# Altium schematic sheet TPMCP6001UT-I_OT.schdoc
size 127 x 101 mm
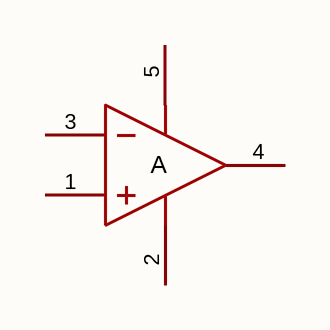
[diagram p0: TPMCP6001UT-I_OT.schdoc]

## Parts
U?  tpmcp6001ut-i/ot  [SOT-23-5_L2.9-W1.6-P0.95-LS2.8-BR]  (value not drawn)

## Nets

Not connected (* = marked no-connect by the designer): U? 1(+IN) 2(-VS) 3(-IN) 4(OUT) 5(+VS)

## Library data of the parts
U? = tpmcp6001ut-i/ot: 放大器数:1;轨到轨:轨到轨输入,轨到轨输出;增益带宽积(GBW):1MHz;输入失调电压(Vos):5mV;压摆率(SR):4.5V/us;输入偏置电流(Ib):10pA;; Manufacturer: TECH PUBLIC(台舟); AddInBom: yes; ModelId: 7ba65df16e7b4570af156e925f9c37fe; ModelTransform: 114.173,114.173,0,90,0,0,0,0,0; Number of Channels: 1; Maximum Power Supply Range (Vdd-Vss): 7V; Gain Bandwidth Product: 1MHz; Vos - Input Offset Voltage: 5mV; Input Offset Voltage Drift(Vos TC): 2uV/℃; Ib - Input Bias Current: 10pA; Input Voltage Noise Density: 30nV/√Hz@1kHz; Common Mode Rejection Ratio(CMRR): 80dB; Quiescent Current: 55uA; Output Current: 20mA; Single supply: 1.8V~5.5V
